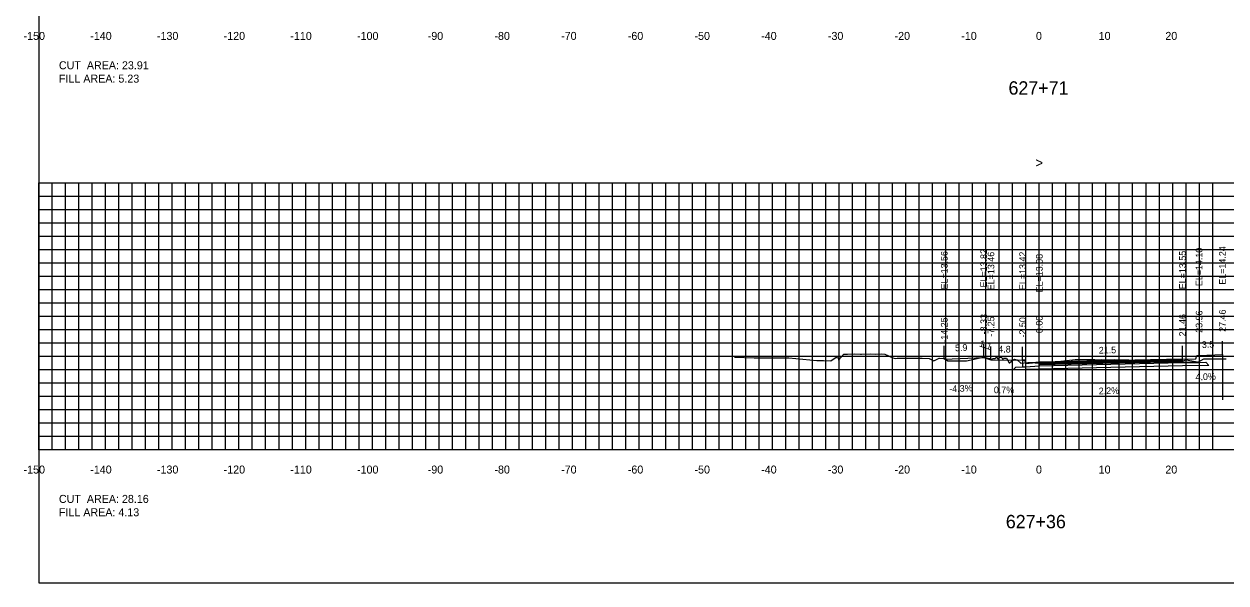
# Model space of a CAD drawing. Extents: x 1797645 to 1803805, y 248417 to 250269.
# Drawn here: x 1802138.8 to 1802319, y 250079.4 to 250163.2 of the extents above; entities that cross this region are included whole.
import ezdxf

# ---------------------------------------------------------------- set-up
doc = ezdxf.new("R2010")
doc.units = 0
for name, color, linetype in [('1', 7, 'Continuous'), ('10', 7, 'Continuous'), ('3', 7, 'Continuous'), ('4', 7, 'Continuous'), ('60', 7, 'Continuous'), ('ANNO-TXT', 7, 'Continuous'), ('BASE', 7, 'Continuous'), ('CL-CNST', 7, 'Continuous'), ('Level 62', 7, 'Continuous'), ('LOWER BINDER', 7, 'Continuous'), ('M-ROADS', 7, 'Continuous'), ('UPPER BINDER', 7, 'Continuous'), ('WEARING', 7, 'Continuous')]:
    doc.layers.add(name, color=color, linetype=linetype)

msp = doc.modelspace()

# ---------------------------------------------------------------- linework, layer by layer
for p, q in [((1802282.67, 250113.25), (1802282.67, 250115.25)), ((1802314.96, 250113.53), (1802314.96, 250115.53)), ((1802318.46, 250113.67), (1802318.46, 250115.67)), ((1802276.75, 250112.99), (1802276.75, 250114.99)), ((1802283.75, 250112.89), (1802283.75, 250114.89)), ((1802288.5, 250112.85), (1802288.5, 250114.85)), ((1802291, 250112.51), (1802291, 250114.51)), ((1802312.47, 250112.99), (1802312.47, 250114.99))]:
    msp.add_line(p, q)
for points in [[(1802141, 250079.43), (1802441, 250079.43), (1802441, 250269.43), (1802141, 250269.43)], [(1802312.47, 250112.99), (1802314.47, 250113.03), (1802314.63, 250113.53), (1802314.96, 250113.53), (1802314.96, 250112.5), (1802314.47, 250112.5), (1802312.47, 250112.46)], [(1802291, 250112.51), (1802289, 250112.35), (1802288.83, 250112.85), (1802288.5, 250112.85), (1802288.5, 250111.82), (1802289, 250111.82), (1802291, 250111.98)]]:
    msp.add_lwpolyline(points, close=True)
at = {"layer": '3'}
msp.add_line((1802318.46, 250113.67), (1802318.46, 250106.88), dxfattribs=at)
at = {"layer": '60'}
for p, q in [((1802140.94, 250139.43), (1802141, 250139.43)), ((1802141, 250099.43), (1802141, 250139.43)), ((1802140.94, 250129.43), (1802141, 250129.43)), ((1802140.94, 250119.43), (1802141, 250119.43)), ((1802140.94, 250109.43), (1802141, 250109.43)), ((1802140.94, 250099.43), (1802141, 250099.43)), ((1802141, 250099.43), (1802441, 250099.43)), ((1802141, 250099.37), (1802141, 250099.43)), ((1802151, 250099.37), (1802151, 250099.43)), ((1802161, 250099.37), (1802161, 250099.43)), ((1802171, 250099.37), (1802171, 250099.43)), ((1802181, 250099.37), (1802181, 250099.43)), ((1802191, 250099.37), (1802191, 250099.43)), ((1802201, 250099.37), (1802201, 250099.43)), ((1802211, 250099.37), (1802211, 250099.43)), ((1802221, 250099.37), (1802221, 250099.43)), ((1802231, 250099.37), (1802231, 250099.43)), ((1802241, 250099.37), (1802241, 250099.43)), ((1802251, 250099.37), (1802251, 250099.43)), ((1802261, 250099.37), (1802261, 250099.43)), ((1802271, 250099.37), (1802271, 250099.43)), ((1802281, 250099.37), (1802281, 250099.43)), ((1802291, 250099.37), (1802291, 250099.43)), ((1802301, 250099.37), (1802301, 250099.43)), ((1802311, 250099.37), (1802311, 250099.43))]:
    msp.add_line(p, q, dxfattribs=at)
at = {"layer": 'BASE'}
msp.add_lwpolyline([(1802291, 250111.98), (1802312.47, 250112.46), (1802314.47, 250112.5), (1802314.96, 250112.5), (1802315.96, 250112.52), (1802316.44, 250112.04), (1802312.47, 250111.96), (1802291, 250111.48), (1802287.09, 250111.4), (1802287.5, 250111.8), (1802288.5, 250111.82), (1802289, 250111.82)], close=True, dxfattribs=at)
at = {"layer": 'CL-CNST'}
msp.add_lwpolyline([(1802276.75, 250112.99), (1802282.67, 250113.25), (1802283.75, 250112.89), (1802288.5, 250112.85), (1802288.83, 250112.85), (1802289, 250112.35), (1802291, 250112.51), (1802312.47, 250112.99), (1802314.47, 250113.03), (1802314.63, 250113.53), (1802314.96, 250113.53), (1802318.46, 250113.67)], dxfattribs=at)
at = {"layer": 'Level 62'}
for p, q in [((1802141, 250139.43), (1802441, 250139.43)), ((1802141, 250099.43), (1802141, 250139.43)), ((1802143, 250099.43), (1802143, 250139.43)), ((1802145, 250099.43), (1802145, 250139.43)), ((1802147, 250099.43), (1802147, 250139.43)), ((1802149, 250099.43), (1802149, 250139.43)), ((1802151, 250099.43), (1802151, 250139.43)), ((1802153, 250099.43), (1802153, 250139.43)), ((1802155, 250099.43), (1802155, 250139.43)), ((1802157, 250099.43), (1802157, 250139.43)), ((1802159, 250099.43), (1802159, 250139.43)), ((1802161, 250099.43), (1802161, 250139.43)), ((1802163, 250099.43), (1802163, 250139.43)), ((1802165, 250099.43), (1802165, 250139.43)), ((1802167, 250099.43), (1802167, 250139.43)), ((1802169, 250099.43), (1802169, 250139.43)), ((1802171, 250099.43), (1802171, 250139.43)), ((1802173, 250099.43), (1802173, 250139.43)), ((1802175, 250099.43), (1802175, 250139.43)), ((1802177, 250099.43), (1802177, 250139.43)), ((1802179, 250099.43), (1802179, 250139.43)), ((1802181, 250099.43), (1802181, 250139.43)), ((1802183, 250099.43), (1802183, 250139.43)), ((1802185, 250099.43), (1802185, 250139.43)), ((1802187, 250099.43), (1802187, 250139.43)), ((1802189, 250099.43), (1802189, 250139.43)), ((1802191, 250099.43), (1802191, 250139.43)), ((1802193, 250099.43), (1802193, 250139.43)), ((1802195, 250099.43), (1802195, 250139.43)), ((1802197, 250099.43), (1802197, 250139.43)), ((1802199, 250099.43), (1802199, 250139.43)), ((1802201, 250099.43), (1802201, 250139.43)), ((1802203, 250099.43), (1802203, 250139.43)), ((1802205, 250099.43), (1802205, 250139.43)), ((1802207, 250099.43), (1802207, 250139.43)), ((1802209, 250099.43), (1802209, 250139.43)), ((1802211, 250099.43), (1802211, 250139.43)), ((1802213, 250099.43), (1802213, 250139.43)), ((1802215, 250099.43), (1802215, 250139.43)), ((1802217, 250099.43), (1802217, 250139.43)), ((1802219, 250099.43), (1802219, 250139.43)), ((1802221, 250099.43), (1802221, 250139.43)), ((1802223, 250099.43), (1802223, 250139.43)), ((1802225, 250099.43), (1802225, 250139.43)), ((1802227, 250099.43), (1802227, 250139.43)), ((1802229, 250099.43), (1802229, 250139.43)), ((1802231, 250099.43), (1802231, 250139.43)), ((1802233, 250099.43), (1802233, 250139.43)), ((1802235, 250099.43), (1802235, 250139.43)), ((1802237, 250099.43), (1802237, 250139.43)), ((1802239, 250099.43), (1802239, 250139.43)), ((1802241, 250099.43), (1802241, 250139.43)), ((1802243, 250099.43), (1802243, 250139.43)), ((1802245, 250099.43), (1802245, 250139.43)), ((1802247, 250099.43), (1802247, 250139.43)), ((1802249, 250099.43), (1802249, 250139.43)), ((1802251, 250099.43), (1802251, 250139.43)), ((1802253, 250099.43), (1802253, 250139.43)), ((1802255, 250099.43), (1802255, 250139.43)), ((1802257, 250099.43), (1802257, 250139.43)), ((1802259, 250099.43), (1802259, 250139.43)), ((1802261, 250099.43), (1802261, 250139.43)), ((1802263, 250099.43), (1802263, 250139.43)), ((1802265, 250099.43), (1802265, 250139.43)), ((1802267, 250099.43), (1802267, 250139.43)), ((1802269, 250099.43), (1802269, 250139.43)), ((1802271, 250099.43), (1802271, 250139.43)), ((1802273, 250099.43), (1802273, 250139.43)), ((1802275, 250099.43), (1802275, 250139.43)), ((1802277, 250099.43), (1802277, 250139.43)), ((1802279, 250099.43), (1802279, 250139.43)), ((1802281, 250099.43), (1802281, 250139.43)), ((1802283, 250099.43), (1802283, 250139.43)), ((1802285, 250099.43), (1802285, 250139.43)), ((1802287, 250099.43), (1802287, 250139.43)), ((1802289, 250099.43), (1802289, 250139.43)), ((1802291, 250099.43), (1802291, 250139.43)), ((1802293, 250099.43), (1802293, 250139.43)), ((1802295, 250099.43), (1802295, 250139.43)), ((1802297, 250099.43), (1802297, 250139.43)), ((1802299, 250099.43), (1802299, 250139.43)), ((1802301, 250099.43), (1802301, 250139.43)), ((1802303, 250099.43), (1802303, 250139.43)), ((1802305, 250099.43), (1802305, 250139.43)), ((1802307, 250099.43), (1802307, 250139.43)), ((1802309, 250099.43), (1802309, 250139.43)), ((1802311, 250099.43), (1802311, 250139.43)), ((1802313, 250099.43), (1802313, 250139.43)), ((1802315, 250099.43), (1802315, 250139.43)), ((1802317, 250099.43), (1802317, 250139.43)), ((1802141, 250137.43), (1802441, 250137.43)), ((1802141, 250135.43), (1802441, 250135.43)), ((1802141, 250133.43), (1802441, 250133.43)), ((1802141, 250131.43), (1802441, 250131.43)), ((1802141, 250129.43), (1802441, 250129.43)), ((1802141, 250127.43), (1802441, 250127.43)), ((1802141, 250125.43), (1802441, 250125.43)), ((1802141, 250123.43), (1802441, 250123.43)), ((1802141, 250121.43), (1802441, 250121.43)), ((1802141, 250119.43), (1802441, 250119.43)), ((1802141, 250117.43), (1802441, 250117.43)), ((1802141, 250115.43), (1802441, 250115.43)), ((1802141, 250113.43), (1802441, 250113.43)), ((1802141, 250111.43), (1802441, 250111.43)), ((1802141, 250109.43), (1802441, 250109.43)), ((1802141, 250107.43), (1802441, 250107.43)), ((1802141, 250105.43), (1802441, 250105.43)), ((1802141, 250103.43), (1802441, 250103.43)), ((1802141, 250101.43), (1802441, 250101.43)), ((1802141, 250099.43), (1802441, 250099.43))]:
    msp.add_line(p, q, dxfattribs=at)
at = {"layer": 'LOWER BINDER'}
msp.add_lwpolyline([(1802312.47, 250112.46), (1802312.47, 250112.46), (1802312.47, 250112.65), (1802291, 250112.17), (1802291, 250111.98)], close=True, dxfattribs=at)
at = {"layer": 'M-ROADS'}
msp.add_lwpolyline([(1802245.32, 250113.29), (1802248.27, 250113.19), (1802248.75, 250113.18), (1802249.37, 250113.18), (1802250.74, 250113.18), (1802252.57, 250113.18), (1802253.44, 250113.18), (1802257.66, 250112.79), (1802258.63, 250112.76), (1802259.75, 250112.75), (1802260.54, 250113.29), (1802260.87, 250113.15), (1802260.88, 250112.81), (1802261.69, 250113.74), (1802261.83, 250113.74), (1802262.22, 250113.75), (1802263.26, 250113.77), (1802264.19, 250113.74), (1802264.32, 250113.74), (1802265.66, 250113.77), (1802266.48, 250113.75), (1802267.28, 250113.77), (1802267.86, 250113.72), (1802269.06, 250113.16), (1802269.42, 250113.1), (1802269.69, 250113.15), (1802271.13, 250113.15), (1802273.43, 250113.13), (1802274.5, 250113.1), (1802275.2, 250112.72), (1802276, 250113.11), (1802276.05, 250113.13), (1802276.85, 250113.06), (1802277.29, 250112.74), (1802277.67, 250112.73), (1802277.75, 250112.72), (1802279.53, 250112.72), (1802280.08, 250112.73), (1802281.21, 250112.96), (1802282.58, 250113.26), (1802283.6, 250113.1), (1802283.76, 250112.91), (1802284.07, 250113.08), (1802284.37, 250113.07), (1802284.53, 250113.25), (1802284.59, 250113.26), (1802284.86, 250112.89), (1802285, 250113.26), (1802285.35, 250113.22), (1802285.53, 250113.04), (1802285.55, 250112.89), (1802285.62, 250113.11), (1802286.06, 250113.11), (1802286.49, 250112.42), (1802286.55, 250112.45), (1802287.03, 250112.81), (1802287.3, 250112.97), (1802287.67, 250112.89), (1802288.24, 250112.4), (1802289.29, 250112.47), (1802289.64, 250112.46), (1802289.77, 250112.47), (1802290.1, 250112.49), (1802290.36, 250112.43), (1802290.85, 250112.45), (1802292.45, 250112.46), (1802292.5, 250112.46), (1802295.14, 250112.78), (1802296.39, 250112.91), (1802297.42, 250112.93), (1802298.09, 250112.95), (1802298.29, 250112.92), (1802299.3, 250112.92), (1802299.41, 250112.9), (1802300.32, 250112.95), (1802301.25, 250112.89), (1802301.32, 250112.9), (1802301.6, 250112.89), (1802301.97, 250112.9), (1802302.24, 250112.91), (1802304.31, 250112.9), (1802304.35, 250112.9), (1802304.45, 250112.9), (1802309.88, 250112.54), (1802311.78, 250112.52), (1802311.99, 250112.52), (1802312.06, 250112.52), (1802312.73, 250112.78), (1802312.97, 250112.88), (1802313.34, 250112.83), (1802314.65, 250112.58), (1802314.84, 250112.53), (1802314.87, 250112.56), (1802315.66, 250113.02), (1802317.22, 250113.02), (1802319, 250113.05)], dxfattribs=at)
at = {"layer": 'UPPER BINDER'}
msp.add_lwpolyline([(1802312.47, 250112.65), (1802312.47, 250112.84), (1802291, 250112.36), (1802291, 250112.17)], close=True, dxfattribs=at)
at = {"layer": 'WEARING'}
msp.add_lwpolyline([(1802312.47, 250112.84), (1802312.47, 250112.99), (1802291, 250112.51), (1802291, 250112.36)], close=True, dxfattribs=at)

# ---------------------------------------------------------------- texts
at = {"layer": '1'}
for s, p in [('627+71', (1802286.38, 250152.63)), ('627+36', (1802285.98, 250087.63))]:
    msp.add_text(s, height=2, dxfattribs=at).set_placement(p)
at = {"layer": '10'}
for s, p in [('-150', (1802138.7, 250160.83)), ('-140', (1802148.7, 250160.83)), ('-130', (1802158.7, 250160.83)), ('-120', (1802168.7, 250160.83)), ('-110', (1802178.7, 250160.83)), ('-100', (1802188.7, 250160.83)), ('-90', (1802199.3, 250160.83)), ('-80', (1802209.3, 250160.83)), ('-70', (1802219.3, 250160.83)), ('-60', (1802229.3, 250160.83)), ('-50', (1802239.3, 250160.83)), ('-40', (1802249.3, 250160.83)), ('-30', (1802259.3, 250160.83)), ('-20', (1802269.3, 250160.83)), ('-10', (1802279.3, 250160.83)), ('0', (1802290.5, 250160.83)), ('10', (1802299.9, 250160.83)), ('20', (1802309.9, 250160.83)), ('-150', (1802138.7, 250095.83)), ('-140', (1802148.7, 250095.83)), ('-130', (1802158.7, 250095.83)), ('-120', (1802168.7, 250095.83)), ('-110', (1802178.7, 250095.83)), ('-100', (1802188.7, 250095.83)), ('-90', (1802199.3, 250095.83)), ('-80', (1802209.3, 250095.83)), ('-70', (1802219.3, 250095.83)), ('-60', (1802229.3, 250095.83)), ('-50', (1802239.3, 250095.83)), ('-40', (1802249.3, 250095.83)), ('-30', (1802259.3, 250095.83)), ('-20', (1802269.3, 250095.83)), ('-10', (1802279.3, 250095.83)), ('0', (1802290.5, 250095.83)), ('10', (1802299.9, 250095.83)), ('20', (1802309.9, 250095.83))]:
    msp.add_text(s, height=1.2, dxfattribs=at).set_placement(p)
at = {"layer": '3'}
for s, p in [('EL=14.24', (1802318.96, 250124.14)), ('EL=13.56', (1802277.25, 250123.42)), ('EL=13.82', (1802283.17, 250123.72)), ('EL=13.46', (1802284.25, 250123.31)), ('EL=13.42', (1802289, 250123.33)), ('EL=13.08', (1802291.5, 250122.99)), ('EL=13.55', (1802312.97, 250123.46)), ('EL=14.10', (1802315.46, 250123.92)), ('-14.25', (1802277.25, 250115.45)), ('-8.33', (1802283.17, 250116.7)), ('-7.25', (1802284.25, 250116.34)), ('-2.50', (1802289, 250116.22)), ('0.00', (1802291.5, 250116.88)), ('21.46', (1802312.97, 250116.39)), ('23.96', (1802315.46, 250116.93)), ('27.46', (1802318.96, 250117.07))]:
    msp.add_text(s, height=1, rotation=90, dxfattribs=at).set_placement(p)
at = {"layer": '4'}
for s, rotation, p in [('5.9', 2.4611, (1802278.38, 250114.16)), ('1.1', 341.5651, (1802281.91, 250114.92)), ('3.5', 2.2906, (1802315.39, 250114.65)), ('4.8', 359.5978, (1802284.85, 250113.98)), ('21.5', 1.2603, (1802299.93, 250113.81)), ('4.0%', 2.2906, (1802314.44, 250109.79)), ('-4.3%', 2.4611, (1802277.52, 250108.02)), ('0.7%', 359.5978, (1802284.18, 250107.88)), ('2.2%', 1.2603, (1802299.93, 250107.71))]:
    msp.add_text(s, height=1, rotation=rotation, dxfattribs=at).set_placement(p)
at = {"layer": '60'}
for s, height, p in [('>', 1.5, (1802290.39, 250141.68)), ('-', 0.0001, (1802141, 250099.43))]:
    msp.add_text(s, height=height, dxfattribs=at).set_placement(p)
at = {"layer": 'ANNO-TXT'}
for s, p in [('CUT  AREA: 23.91', (1802144, 250156.43)), ('FILL AREA: 5.23', (1802144, 250154.43)), ('CUT  AREA: 28.16', (1802144, 250091.43)), ('FILL AREA: 4.13', (1802144, 250089.43))]:
    msp.add_text(s, height=1.2, dxfattribs=at).set_placement(p)

doc.saveas('drawing.dxf')
